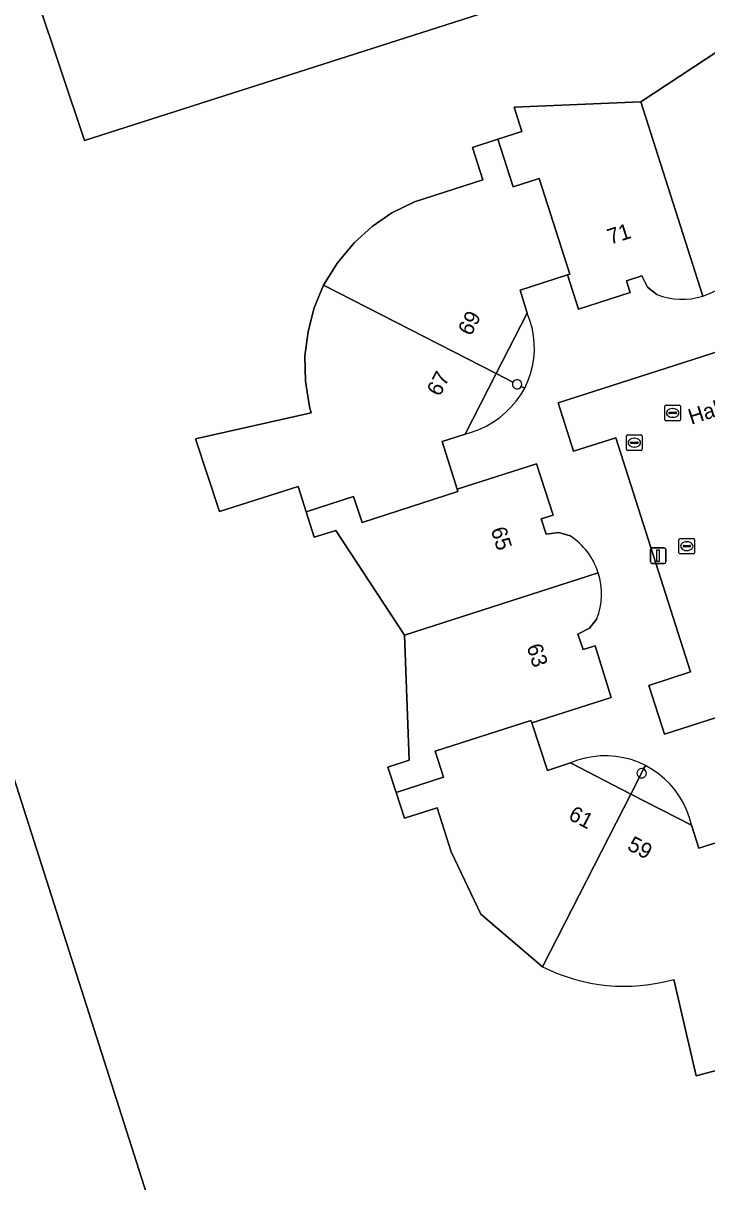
# Model space of a CAD drawing. Extents: x 159499 to 160349, y 382524 to 383273.
# Drawn here: x 159623.7 to 159667.6, y 382799.5 to 382873.9 of the extents above; entities that cross this region are included whole.
import ezdxf

# ---------------------------------------------------------------- set-up
doc = ezdxf.new("R2010")
doc.units = 0
for name, color, linetype in [('IMGEO_Brandkraan', 7, 'Continuous'), ('IMGEO_Erf', 7, 'Continuous'), ('IMGEO_Lichtmast', 7, 'Continuous'), ('IMGEO_Openbare_ruimte_label', 7, 'Continuous'), ('IMGEO_Pand', 7, 'Continuous'), ('IMGEO_Pand_nummerreeks', 7, 'Continuous'), ('IMGEO_Pand_overbouw', 7, 'Continuous'), ('IMGEO_Rijbaan_lokaal_open', 7, 'Continuous'), ('IMGEO_Rioolput', 7, 'Continuous')]:
    doc.layers.add(name, color=color, linetype=linetype)

msp = doc.modelspace()

# ---------------------------------------------------------------- linework, layer by layer
at = {"layer": 'IMGEO_Brandkraan'}
for p, q in [((159665.805, 382839.896), (159665.805, 382840.748)), ((159665.88, 382840.822), (159666.732, 382840.822)), ((159666.806, 382840.748), (159666.806, 382839.896)), ((159666.064, 382840.316), (159666.064, 382840.328)), ((159666.502, 382840.279), (159666.104, 382840.279)), ((159666.107, 382840.365), (159666.505, 382840.365)), ((159666.316, 382840.042), (159666.291, 382840.042)), ((159666.293, 382840.602), (159666.318, 382840.602)), ((159666.548, 382840.328), (159666.548, 382840.316)), ((159666.732, 382839.822), (159665.88, 382839.822))]:
    msp.add_line(p, q, dxfattribs=at)
for points in [[(159665.805, 382839.896), (159665.805, 382840.748)], [(159665.88, 382840.822), (159666.732, 382840.822)], [(159666.806, 382840.748), (159666.806, 382839.896)], [(159666.732, 382839.822), (159665.88, 382839.822)]]:
    msp.add_lwpolyline(points, dxfattribs=at)
for centre, radius, start, end in [((159665.882, 382840.746), 0.0765, 91.55205, 178.44795), ((159665.882, 382840.746), 0.0765, 91.55205, 178.44795), ((159666.73, 382840.746), 0.0765, 1.55205, 88.44795), ((159666.73, 382840.746), 0.0765, 1.55205, 88.44795), ((159665.882, 382839.898), 0.0765, 181.55205, 268.44795), ((159665.882, 382839.898), 0.0765, 181.55205, 268.44795), ((159666.104, 382840.325), 0.0403, 85.87752, 175.75265), ((159666.101, 382840.315), 0.0366, 178.93798, 274.71019), ((159666.505, 382840.322), 0.043, 264.86636, 352.45326), ((159666.509, 382840.327), 0.0386, 1.73085, 96.63898), ((159666.73, 382839.898), 0.0765, 271.55205, 358.44795), ((159666.73, 382839.898), 0.0765, 271.55205, 358.44795)]:
    msp.add_arc(centre, radius, start, end, dxfattribs=at)
for centre, major_axis, ratio, start_param, end_param in [((159666.292, 382840.322), (-0.387, 0.002), 0.722429, 4.712389, 7.853982), ((159666.317, 382840.322), (-0.39, 0.002), 0.717154, 1.570796, 4.712389)]:
    msp.add_ellipse(centre, major_axis=major_axis, ratio=ratio, start_param=start_param, end_param=end_param, dxfattribs=at)
at = {"layer": 'IMGEO_Erf'}
for points in [[(159677.627, 382884.962), (159674.658, 382884.016), (159673.774, 382886.788), (159652.977, 382879.994), (159654.595, 382874.974), (159627.613, 382866.357), (159623.043, 382880.046), (159623.336, 382880.144), (159623.263, 382880.365), (159621.679, 382885.107), (159616.505, 382883.25), (159614.32, 382889.33), (159646.264, 382900.819), (159647.798, 382896.061), (159652.453, 382881.618), (159666.269, 382885.977), (159665.394, 382888.751), (159669.71, 382890.113), (159670.586, 382887.339), (159686.697, 382892.422), (159684.344, 382903.803), (159682.972, 382908.111), (159679.314, 382919.635)], [(159657.049, 382813.325), (159653.07, 382816.707), (159651.177, 382820.713), (159650.284, 382823.533), (159648.172, 382822.875), (159647.638, 382824.509), (159647.107, 382826.134), (159648.474, 382826.593), (159648.169, 382834.606), (159643.763, 382841.319), (159642.369, 382840.898), (159641.853, 382842.528), (159641.34, 382844.146), (159636.304, 382842.557), (159634.757, 382847.218), (159642.187, 382848.871), (159642.066, 382849.257), (159641.807, 382850.914), (159641.785, 382852.509), (159641.981, 382854.092), (159642.38, 382855.615), (159642.982, 382857.07), (159643.87, 382858.517), (159644.967, 382859.814), (159646.096, 382860.846), (159647.355, 382861.716), (159648.826, 382862.427), (159653.209, 382863.826), (159652.535, 382865.902), (159654.175, 382866.438), (159655.721, 382866.944), (159655.209, 382868.508), (159663.352, 382868.835), (159670.048, 382873.242)], [(159706.174, 382845.013), (159707.207, 382841.819), (159705.912, 382841.405), (159664.868, 382828.266), (159663.864, 382831.383), (159666.542, 382832.265), (159661.739, 382847.267), (159659.033, 382846.414), (159658.047, 382849.524), (159699.119, 382862.705), (159700.405, 382863.118), (159700.812, 382861.848)], [(159664.385, 382856.471), (159663.784, 382856.944), (159663.413, 382857.68), (159662.43, 382857.358), (159662.673, 382856.596), (159659.36, 382855.539), (159658.648, 382857.742), (159655.595, 382856.758), (159656.059, 382855.281), (159654.063, 382851.403), (159652.063, 382847.517), (159650.586, 382847.038), (159651.562, 382843.973), (159656.652, 382845.616), (159657.718, 382842.319), (159656.949, 382842.067), (159657.275, 382841.088), (159658.083, 382841.205), (159658.817, 382840.982)], [(159610.474, 382773.686), (159591.185, 382834.035), (159595.948, 382835.557), (159617.624, 382842.485), (159636.889, 382782.21)], [(159660.525, 382835.656), (159660.06, 382835.05), (159659.319, 382834.671), (159659.644, 382833.689), (159660.417, 382833.93), (159661.452, 382830.613), (159656.347, 382828.991), (159657.362, 382825.93), (159658.83, 382826.406), (159662.712, 382824.41), (159666.599, 382822.412), (159667.071, 382820.931), (159670.133, 382821.912), (159669.419, 382824.112), (159672.736, 382825.178), (159672.993, 382824.399), (159673.966, 382824.727), (159673.846, 382825.549), (159674.066, 382826.268)], [(159680.409, 382815.596), (159673.89, 382811.313), (159674.339, 382809.721), (159670.881, 382808.621), (159671.251, 382807.474), (159666.907, 382806.328), (159665.465, 382812.52)]]:
    msp.add_lwpolyline(points, dxfattribs=at)
for centre, radius, start, end in [((159665.996, 382860.536), 4.371, 287.79581, 327.80629), ((159665.994, 382860.544), 4.379, 248.4404, 287.7892), ((159655.394, 382850.71), 0.29, 150.72283, 180.45695), ((159655.404, 382850.709), 0.3, 180.16502, 334.37395), ((159655.404, 382850.708), 0.3, 359.92004, 151.38574), ((159655.414, 382850.705), 0.29, 334.13485, 0.52552), ((159656.398, 382837.269), 4.432, 17.73946, 56.91809), ((159656.396, 382837.27), 4.433, 338.64951, 17.71634), ((159663.408, 382825.751), 0.3, 64.68977, 179.99238), ((159663.409, 382825.751), 0.301, 180.09251, 240.93374), ((159663.407, 382825.752), 0.301, 241.3885, 359.77863), ((159663.408, 382825.751), 0.3, 0.02439, 64.78109), ((159662.284, 382823.655), 11.58, 243.12618, 285.94625)]:
    msp.add_arc(centre, radius, start, end, dxfattribs=at)
at = {"layer": 'IMGEO_Lichtmast'}
for p, q in [((159663.968, 382839.31), (159663.968, 382840.11)), ((159663.968, 382840.11), (159663.968, 382839.31)), ((159664.068, 382840.21), (159664.858, 382840.21)), ((159664.858, 382840.21), (159664.068, 382840.21)), ((159664.958, 382840.11), (159664.958, 382839.31)), ((159664.958, 382839.31), (159664.958, 382840.11)), ((159664.858, 382839.21), (159664.068, 382839.21)), ((159664.068, 382839.21), (159664.858, 382839.21))]:
    msp.add_line(p, q, dxfattribs=at)
msp.add_lwpolyline([(159664.388, 382840.085), (159664.538, 382840.085), (159664.538, 382839.335), (159664.388, 382839.335), (159664.388, 382840.085)], dxfattribs=at)
for centre, start, end in [((159664.068, 382840.11), 90, 180), ((159664.068, 382840.11), 90, 180), ((159664.858, 382840.11), 0, 90), ((159664.858, 382840.11), 360, 90), ((159664.068, 382839.31), 180, 270), ((159664.068, 382839.31), 180, 270), ((159664.858, 382839.31), 270, 0), ((159664.858, 382839.31), 270, 0)]:
    msp.add_arc(centre, 0.1, start, end, dxfattribs=at)
at = {"layer": 'IMGEO_Pand'}
for points in [[(159647.798, 382896.061), (159646.264, 382900.819), (159614.32, 382889.33), (159616.505, 382883.25), (159621.679, 382885.107), (159623.263, 382880.365), (159623.336, 382880.144), (159623.043, 382880.046), (159627.613, 382866.357), (159654.595, 382874.974), (159652.977, 382879.994), (159652.453, 382881.618)], [(159656.822, 382863.928), (159655.152, 382863.392), (159654.175, 382866.438), (159652.535, 382865.902), (159653.209, 382863.826), (159648.826, 382862.427), (159647.355, 382861.716), (159646.096, 382860.846), (159644.967, 382859.814), (159643.87, 382858.517), (159642.982, 382857.07), (159654.063, 382851.403), (159656.059, 382855.281), (159655.595, 382856.758), (159658.648, 382857.742), (159658.791, 382857.788)], [(159654.063, 382851.403), (159642.982, 382857.07), (159642.38, 382855.615), (159641.981, 382854.092), (159641.785, 382852.509), (159641.807, 382850.914), (159642.066, 382849.257), (159642.187, 382848.871), (159634.757, 382847.218), (159636.304, 382842.557), (159641.34, 382844.146), (159641.853, 382842.528), (159644.908, 382843.515), (159645.45, 382841.84), (159651.608, 382843.83), (159651.562, 382843.973), (159650.586, 382847.038), (159652.063, 382847.517)], [(159656.347, 382828.991), (159656.3, 382829.133), (159650.152, 382827.16), (159650.688, 382825.488), (159647.638, 382824.509), (159648.172, 382822.875), (159650.284, 382823.533), (159651.177, 382820.713), (159653.07, 382816.707), (159657.049, 382813.325), (159662.712, 382824.41), (159658.83, 382826.406), (159657.362, 382825.93)]]:
    msp.add_lwpolyline(points, close=True, dxfattribs=at)
for points in [[(159669.695, 382858.207), (159669.909, 382858.918), (159669.789, 382859.732), (159670.764, 382860.048), (159671.03, 382859.278), (159674.193, 382860.293), (159670.048, 382873.242), (159663.352, 382868.835), (159667.332, 382856.374)], [(159667.332, 382856.374), (159663.352, 382868.835), (159655.209, 382868.508), (159655.721, 382866.944), (159654.175, 382866.438), (159655.152, 382863.392), (159656.822, 382863.928), (159658.791, 382857.788), (159658.648, 382857.742), (159659.36, 382855.539), (159662.673, 382856.596), (159662.43, 382857.358), (159663.413, 382857.68), (159663.784, 382856.944), (159664.385, 382856.471)], [(159658.817, 382840.982), (159658.083, 382841.205), (159657.275, 382841.088), (159656.949, 382842.067), (159657.718, 382842.319), (159656.652, 382845.616), (159651.562, 382843.973), (159651.608, 382843.83), (159645.45, 382841.84), (159644.908, 382843.515), (159641.853, 382842.528), (159642.369, 382840.898), (159643.763, 382841.319), (159648.169, 382834.606), (159660.619, 382838.619)], [(159636.889, 382782.21), (159617.624, 382842.485), (159595.948, 382835.557), (159591.185, 382834.035), (159610.474, 382773.686)], [(159660.619, 382838.619), (159648.169, 382834.606), (159648.474, 382826.593), (159647.107, 382826.134), (159647.638, 382824.509), (159650.688, 382825.488), (159650.152, 382827.16), (159656.3, 382829.133), (159656.347, 382828.991), (159661.452, 382830.613), (159660.417, 382833.93), (159659.644, 382833.689), (159659.319, 382834.671), (159660.06, 382835.05), (159660.525, 382835.656)], [(159663.263, 382825.488), (159663.536, 382826.022)], [(159663.536, 382826.022), (159663.263, 382825.488)], [(159665.465, 382812.52), (159666.907, 382806.328), (159671.251, 382807.474), (159670.881, 382808.621), (159669.914, 382811.62), (159671.543, 382812.138), (159670.561, 382815.223), (159672.248, 382815.759), (159670.276, 382821.958), (159670.133, 382821.912), (159667.071, 382820.931), (159666.599, 382822.412), (159662.712, 382824.41), (159657.049, 382813.325)]]:
    msp.add_lwpolyline(points, dxfattribs=at)
for centre, radius, start, end in [((159665.996, 382860.536), 4.371, 287.79581, 327.80629), ((159665.994, 382860.544), 4.379, 248.4404, 287.7892), ((159655.394, 382850.71), 0.29, 150.72283, 180.45695), ((159655.404, 382850.709), 0.3, 180.16502, 334.37395), ((159655.404, 382850.708), 0.3, 359.92004, 151.38574), ((159655.414, 382850.705), 0.29, 334.13485, 0.52552), ((159656.398, 382837.269), 4.432, 17.73946, 56.91809), ((159656.396, 382837.27), 4.433, 338.64951, 17.71634), ((159663.408, 382825.751), 0.3, 64.68977, 179.99238), ((159663.409, 382825.751), 0.301, 180.09251, 240.93374), ((159663.407, 382825.752), 0.301, 241.3885, 359.77863), ((159663.408, 382825.751), 0.3, 0.02439, 64.78109), ((159662.284, 382823.655), 11.58, 243.12618, 285.94625)]:
    msp.add_arc(centre, radius, start, end, dxfattribs=at)
at = {"layer": 'IMGEO_Pand_overbouw'}
for points in [[(159655.675, 382850.579), (159655.898, 382850.465), (159656.105, 382850.917), (159656.271, 382851.386), (159656.396, 382851.868), (159656.478, 382852.359), (159656.517, 382852.855), (159656.512, 382853.352), (159656.463, 382853.848), (159656.37, 382854.337), (159656.235, 382854.816), (159656.059, 382855.281), (159654.063, 382851.403), (159655.141, 382850.852)], [(159655.141, 382850.852), (159654.063, 382851.403), (159652.063, 382847.517), (159652.541, 382847.656), (159653.006, 382847.833), (159653.455, 382848.049), (159653.884, 382848.301), (159654.291, 382848.587), (159654.672, 382848.907), (159655.026, 382849.257)], [(159655.026, 382849.257), (159655.35, 382849.635), (159655.641, 382850.039), (159655.898, 382850.465), (159655.675, 382850.579)], [(159663.536, 382826.022), (159663.65, 382826.246), (159663.197, 382826.453), (159662.728, 382826.62), (159662.246, 382826.745), (159661.754, 382826.827), (159661.258, 382826.865), (159660.76, 382826.86), (159660.264, 382826.811), (159659.775, 382826.718), (159659.296, 382826.583), (159658.83, 382826.406), (159662.712, 382824.41), (159663.263, 382825.488)], [(159663.263, 382825.488), (159662.712, 382824.41), (159666.599, 382822.412), (159666.471, 382822.895), (159666.302, 382823.365), (159666.091, 382823.818), (159665.842, 382824.251), (159665.555, 382824.66), (159665.233, 382825.042), (159664.879, 382825.394), (159664.495, 382825.714), (159664.084, 382825.998), (159663.65, 382826.246), (159663.536, 382826.022)]]:
    msp.add_lwpolyline(points, dxfattribs=at)
for centre, radius, start, end in [((159655.394, 382850.71), 0.29, 150.72283, 180.45695), ((159655.404, 382850.709), 0.3, 180.16502, 334.37395), ((159655.404, 382850.708), 0.3, 359.92004, 151.38574), ((159655.414, 382850.705), 0.29, 334.13485, 0.52552), ((159663.408, 382825.751), 0.3, 64.68977, 179.99238), ((159663.409, 382825.751), 0.301, 180.09251, 240.93374), ((159663.407, 382825.752), 0.301, 241.3885, 359.77863), ((159663.405, 382825.749), 0.303, 0.37797, 64.42751)]:
    msp.add_arc(centre, radius, start, end, dxfattribs=at)
at = {"layer": 'IMGEO_Rijbaan_lokaal_open'}
msp.add_lwpolyline([(159699.712, 382860.799), (159699.119, 382862.705), (159658.047, 382849.524), (159659.033, 382846.414), (159661.739, 382847.267), (159666.542, 382832.265), (159663.864, 382831.383), (159664.868, 382828.266), (159705.912, 382841.405), (159704.996, 382844.273)], dxfattribs=at)
at = {"layer": 'IMGEO_Rioolput'}
for p, q in [((159664.901, 382848.448), (159664.901, 382849.3)), ((159664.976, 382849.374), (159665.828, 382849.374)), ((159665.16, 382848.868), (159665.16, 382848.88)), ((159665.598, 382848.831), (159665.2, 382848.831)), ((159665.203, 382848.917), (159665.601, 382848.917)), ((159665.389, 382849.154), (159665.414, 382849.154)), ((159665.644, 382848.88), (159665.644, 382848.868)), ((159665.902, 382849.3), (159665.902, 382848.448)), ((159665.828, 382848.374), (159664.976, 382848.374)), ((159665.412, 382848.594), (159665.387, 382848.594)), ((159662.437, 382846.538), (159662.437, 382847.39)), ((159662.512, 382847.464), (159663.364, 382847.464)), ((159663.438, 382847.39), (159663.438, 382846.538)), ((159662.696, 382846.958), (159662.696, 382846.97)), ((159663.134, 382846.921), (159662.736, 382846.921)), ((159662.739, 382847.007), (159663.137, 382847.007)), ((159662.948, 382846.684), (159662.923, 382846.684)), ((159662.925, 382847.244), (159662.95, 382847.244)), ((159663.18, 382846.97), (159663.18, 382846.958)), ((159663.364, 382846.464), (159662.512, 382846.464))]:
    msp.add_line(p, q, dxfattribs=at)
for points in [[(159664.901, 382848.448), (159664.901, 382849.3)], [(159664.976, 382849.374), (159665.828, 382849.374)], [(159665.902, 382849.3), (159665.902, 382848.448)], [(159665.828, 382848.374), (159664.976, 382848.374)], [(159662.437, 382846.538), (159662.437, 382847.39)], [(159662.512, 382847.464), (159663.364, 382847.464)], [(159663.438, 382847.39), (159663.438, 382846.538)], [(159663.364, 382846.464), (159662.512, 382846.464)]]:
    msp.add_lwpolyline(points, dxfattribs=at)
for centre, radius, start, end in [((159664.978, 382849.298), 0.0765, 91.55205, 178.44795), ((159664.978, 382849.298), 0.0765, 91.55205, 178.44795), ((159665.2, 382848.877), 0.0403, 85.87752, 175.75265), ((159665.197, 382848.867), 0.0366, 178.93798, 274.71019), ((159665.601, 382848.874), 0.043, 264.86636, 352.45326), ((159665.605, 382848.879), 0.0386, 1.73085, 96.63898), ((159665.826, 382849.298), 0.0765, 1.55205, 88.44795), ((159665.826, 382849.298), 0.0765, 1.55205, 88.44795), ((159664.978, 382848.45), 0.0765, 181.55205, 268.44795), ((159664.978, 382848.45), 0.0765, 181.55205, 268.44795), ((159665.826, 382848.45), 0.0765, 271.55205, 358.44795), ((159665.826, 382848.45), 0.0765, 271.55205, 358.44795), ((159662.514, 382847.388), 0.0765, 91.55205, 178.44795), ((159662.514, 382847.388), 0.0765, 91.55205, 178.44795), ((159663.362, 382847.388), 0.0765, 1.55205, 88.44795), ((159663.362, 382847.388), 0.0765, 1.55205, 88.44795), ((159662.736, 382846.967), 0.0403, 85.87752, 175.75265), ((159662.733, 382846.957), 0.0366, 178.93798, 274.71019), ((159663.137, 382846.964), 0.043, 264.86636, 352.45326), ((159663.141, 382846.969), 0.0386, 1.73085, 96.63898), ((159662.514, 382846.54), 0.0765, 181.55205, 268.44795), ((159662.514, 382846.54), 0.0765, 181.55205, 268.44795), ((159663.362, 382846.54), 0.0765, 271.55205, 358.44795), ((159663.362, 382846.54), 0.0765, 271.55205, 358.44795)]:
    msp.add_arc(centre, radius, start, end, dxfattribs=at)
for centre, major_axis, ratio, start_param, end_param in [((159665.388, 382848.874), (-0.387, 0.002), 0.722429, 4.712389, 7.853982), ((159665.413, 382848.874), (-0.39, 0.002), 0.717154, 1.570796, 4.712389), ((159662.924, 382846.964), (-0.387, 0.002), 0.722429, 4.712389, 7.853982), ((159662.949, 382846.964), (-0.39, 0.002), 0.717154, 1.570796, 4.712389)]:
    msp.add_ellipse(centre, major_axis=major_axis, ratio=ratio, start_param=start_param, end_param=end_param, dxfattribs=at)

# ---------------------------------------------------------------- texts
at = {"layer": 'IMGEO_Openbare_ruimte_label'}
msp.add_text('Habsburglaan', height=1, rotation=17.74685, dxfattribs=at).set_placement((159666.589, 382848.113))
at = {"layer": 'IMGEO_Pand_nummerreeks'}
for s, rotation, p in [('71', 17.77182, (159661.391, 382859.669)), ('69', 62.76588, (159652.441, 382853.759)), ('67', 62.76588, (159650.443, 382849.877)), ('65', 287.74135, (159653.703, 382841.381)), ('63', 287.74135, (159656.008, 382833.881)), ('61', 332.79256, (159658.637, 382822.816)), ('59', 332.79256, (159662.422, 382820.871))]:
    msp.add_text(s, height=1, rotation=rotation, dxfattribs=at).set_placement(p)

doc.saveas('drawing.dxf')
